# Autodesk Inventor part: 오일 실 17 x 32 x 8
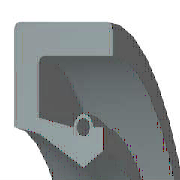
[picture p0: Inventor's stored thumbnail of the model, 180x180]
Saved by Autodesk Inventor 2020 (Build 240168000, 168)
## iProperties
IsCustomPart: 1
Created: 2012-02
Part Number: 오일 실 17 x 32 x 8
Material: 고무
Description: 오일-실
Document SubType Name: Modeling
Standard: KS B 2804
Designer: test
Standards Organization: KS
Language: ko-KR
Size Designation: S - 17 32 8
Categories: <MemberInstance><Categories><Category DisplayName="샤프트 부품" InternalName="7f7aeb1f-a693-4053-b835-cee3144e0d98" Mnemonic="SHFT"><Category DisplayName="실링" Intern
Density: 0.93 g/cm^3
Appearance: 고무 - 검은색 - 버전 1.1
Author: test
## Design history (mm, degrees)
revolve "본체" stored, may be unused: angle "d17" = 90 deg
revolve "스프링1" stored, may be unused: angle "d18" = 90 deg
body "Solid1"
sketch "스케치1"
  geometry: L1 (0, 16)-(8, 16); L2 (8, 16)-(8, 14.75); L3 (8, 14.75)-(1.75, 14.75); L4 (0, 16)-(0, 10.6); L5 (0, 10.6)-(1.75, 10.25); L6 (1.75, 10.25)-(4.9, 8.5); L7 (4.9, 8.5)-(0, 8.5); L8 (6.3, 9.375)-(6.3, 10.6); L9 (0, 0)-(9.586, 0) reference; L10 (4.9, 8.5)-(6.3, 9.375); L11 (0, 18)-(0, -3) reference; L12 (-1.917, 0)-(11.503, 0) reference; L13 (4.2, 10.6)-(1.75, 11.09); L14 (1.75, 11.09)-(1.75, 14.75); L15 (6.3, 10.6)-(5.6, 10.6); C1 r 0.455 at (4.9, 10.6); A1 r 0.7 centre (4.9, 10.6) between (5.6, 10.6) and (4.2, 10.6)
  constraints: 26 end point, 5 horizontal alignment, 4 perpendicular, 2 centre point, 2 collinear, 2 horizontal, 2 parallel, 2 point on circle, 2 point on line, 2 vertical alignment, 1 coincident
  dimensions: "d0" = 32 diameter of L1 L9 (= SD2); "d1" = 18.75 diameter of L8.start L9 (= ABDM); "d2" = 1.25 distance of L1.end L2.end (computed from SD); "d3" = 0.91 diameter of C1 (= SPDI); "d4" = 1.4 diameter of A1 (= SPDA); "d5" = 17 diameter of L6.end L9 (= NND); "d6" = 20.5 diameter of L5.end L9 (= TKDM); "d7" = 21.2 diameter of L4.end L9 (= HLDM); "d8" = 4.9 distance from line of C1.centre L4 (= SPDST); "d9" = 6.3 distance between parallel lines of L8 L4 (= SDI); "d10" = 8 distance between parallel lines of L2 L4 (= SWDT); "d12" = 1.75 distance between parallel lines of L14 L4 (= SD)
fillet "모깎기1" dims "d11" = 0.3 (= RR)
other parameters: "SD2" = 32 [user parameter; used in 1 equation term], "SWDT" = 8 [user parameter; used in 1 equation term], "RR" = 0.3 [user parameter; used in 1 equation term], "SD" = 1.75 [user parameter; used in 2 equation terms], "NND" = 17 [user parameter; used in 1 equation term], "SPDA" = 1.4 [user parameter; used in 1 equation term], "SPDI" = 0.91 [user parameter; used in 1 equation term], "TKDM" = 20.5 [user parameter; used in 1 equation term], "HLDM" = 21.2 [user parameter; used in 1 equation term], "ABDM" = 18.75 [user parameter; used in 1 equation term], "SDI" = 6.3 [user parameter; used in 1 equation term], "SPDST" = 4.9 [user parameter; used in 1 equation term], "d13" = 0, "d14" = 0, "d15" = 0, "LAB" = 0.35 [user parameter]
